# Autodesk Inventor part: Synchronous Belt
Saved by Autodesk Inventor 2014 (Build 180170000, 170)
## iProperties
Created: 2013-12
Part Number: Synchronous Belt
Material: Rubber
Document SubType Name: Modeling
Designer: Bram
Density: 1 g/cm^3
Appearance: Rubber - Black - Version 1.1
CustomPartVersion: 1
Author: Bram
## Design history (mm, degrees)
sketch "Sketch Path"
  geometry: L1 (-10.901, -546.06)-(-8.085, 0.042); L2 (8.083, -0.185)-(-4.433, -546.15); A1 r 8.085 centre (0, 0) between (8.083, -0.185) and (-8.085, 0.042); A2 r 3.234 centre (-7.667, -546.076) between (-10.901, -546.06) and (-4.433, -546.15)
  constraints: 4 end point, 4 point on circle, 2 centre point
node "Cross Section Plane"
workaxis "Work Axis1"
workaxis "Work Axis2"
workplane "Work Plane2"
workplane "Work Plane3"
sketch "Cross Section"
  geometry: L1 (-3.175, 0.381)-(3.175, 0.381); L2 (3.175, 0.381)-(3.175, -0.254); L3 (3.175, -0.254)-(-3.175, -0.254); L4 (-3.175, -0.254)-(-3.175, 0.381); L5 (-3.175, 0)-(3.175, 0); 2 further points
  constraints: 10 end point, 2 parallel, 2 point on line, 1 coincident, 1 horizontal, 1 midpoint, 1 perpendicular, 1 other
  dimensions: "d0" = 6.35 distance between parallel lines of L2 L4 (= da_B); "d4" = 0.254 distance between parallel lines of L3 L5 (= da_a); "d5" = 0.381 distance between parallel lines of L5 L1 (= da_a2)
feature "Belt" sketch "Cross Section" dims "d2" = 0
body "Solid1"
other parameters: "da_B" = 6.35 [user parameter; used in 1 equation term], "da_pb" = 2.032 [user parameter], "da_L" = 1127.8631 [user parameter], "da_a" = 0.254 [user parameter; used in 1 equation term], "da_S" = 1.143 [user parameter], "da_Beta" = 20 deg [user parameter], "da_Ht" = 0.508 [user parameter], "da_H" = 1.143 [user parameter], "da_a2" = 0.381 [user parameter; used in 1 equation term], "d6" = 0, "d7" = 0, "d8" = 0, "d9" = 0, "d10" = 0
